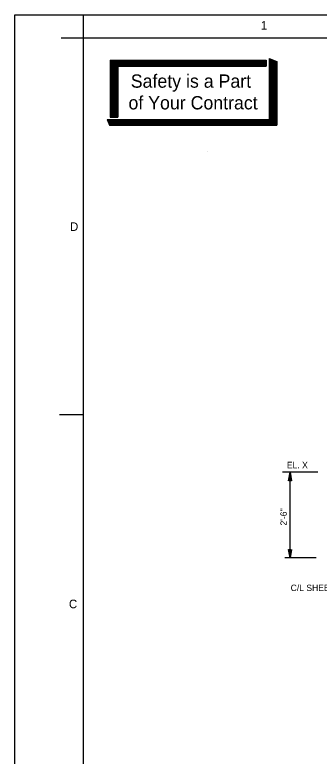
# Model space of a CAD drawing. Extents: x 44743.44 to 44747.1, y 44738.46 to 44741.29.
# Drawn here: x 44743.438 to 44743.993, y 44739.94 to 44741.292 of the extents above; entities that cross this region are included whole.
import ezdxf

# ---------------------------------------------------------------- set-up
doc = ezdxf.new("R2010")
doc.units = 0
for name, color, linetype in [('Level 1', 7, 'Continuous'), ('Level 10', 7, 'Continuous'), ('Level 9', 7, 'Continuous'), ('S-ANNO-TEXT', 7, 'Continuous')]:
    doc.layers.add(name, color=color, linetype=linetype)

msp = doc.modelspace()

# ---------------------------------------------------------------- linework, layer by layer
at = {"layer": 'Level 1'}
for p, q in [((44743.9904, 44740.4576), (44743.9264, 44740.4576)), ((44743.9399, 44740.3015), (44743.9399, 44740.4576)), ((44743.9399, 44740.4576), (44743.9399, 44740.4576)), ((44743.9399, 44740.4533), (44743.9399, 44740.4533)), ((44743.9877, 44740.3015), (44743.9303, 44740.3015)), ((44743.9399, 44740.3058), (44743.9399, 44740.3058)), ((44743.9399, 44740.3015), (44743.9399, 44740.3015))]:
    msp.add_line(p, q, dxfattribs=at)
msp.add_lwpolyline([(44743.438, 44741.2918), (44747.1047, 44741.2918), (44747.1047, 44738.4578), (44743.438, 44738.4578)], close=True, dxfattribs=at)
for points in [[(44743.9373, 44740.4421), (44743.9399, 44740.4576), (44743.9425, 44740.4421), (44743.938, 44740.4421), (44743.9399, 44740.4533), (44743.9416, 44740.4427), (44743.9388, 44740.4427), (44743.9399, 44740.4491), (44743.9408, 44740.4434), (44743.9396, 44740.4434), (44743.9399, 44740.4448)], [(44743.9425, 44740.317), (44743.9399, 44740.3015), (44743.9373, 44740.317), (44743.9417, 44740.317), (44743.9399, 44740.3058), (44743.9381, 44740.3164), (44743.941, 44740.3164), (44743.9399, 44740.31), (44743.939, 44740.3157), (44743.9401, 44740.3157), (44743.9399, 44740.3143)]]:
    msp.add_lwpolyline(points, dxfattribs=at)
at = {"layer": 'Level 10'}
for p, q in [((44743.563, 44741.2498), (44743.563, 44741.2918)), ((44743.5223, 44741.2498), (44743.5626, 44741.2498)), ((44743.612, 44741.2089), (44743.8967, 44741.2089)), ((44743.612, 44741.2089), (44743.612, 44741.1055)), ((44743.612, 44741.2076), (44743.8967, 44741.2076)), ((44743.612, 44741.2064), (44743.8967, 44741.2064)), ((44743.6133, 44741.2089), (44743.6133, 44741.1055)), ((44743.6146, 44741.2089), (44743.6146, 44741.1055)), ((44743.6159, 44741.2089), (44743.6159, 44741.1055)), ((44743.6172, 44741.2089), (44743.6172, 44741.1055)), ((44743.6185, 44741.2089), (44743.6185, 44741.1055)), ((44743.6198, 44741.2089), (44743.6198, 44741.1055)), ((44743.6211, 44741.2089), (44743.6211, 44741.1055)), ((44743.6224, 44741.2089), (44743.6224, 44741.1055)), ((44743.6237, 44741.2089), (44743.6237, 44741.1055)), ((44743.625, 44741.2089), (44743.625, 44741.1055)), ((44743.8967, 44741.2089), (44743.8967, 44741.1985)), ((44743.902, 44741.212), (44743.902, 44741.1009)), ((44743.902, 44741.212), (44743.9159, 44741.2069)), ((44743.9029, 44741.2117), (44743.9029, 44741.0904)), ((44743.9042, 44741.2112), (44743.9042, 44741.0904)), ((44743.9055, 44741.2107), (44743.9055, 44741.0904)), ((44743.9068, 44741.2102), (44743.9068, 44741.0904)), ((44743.9081, 44741.2098), (44743.9081, 44741.0904)), ((44743.9094, 44741.2093), (44743.9094, 44741.0904)), ((44743.9107, 44741.2088), (44743.9107, 44741.0904)), ((44743.912, 44741.2083), (44743.912, 44741.0904)), ((44743.9133, 44741.2079), (44743.9133, 44741.0904)), ((44743.9146, 44741.2069), (44743.9146, 44741.0904)), ((44743.9159, 44741.2069), (44743.9159, 44741.0904)), ((44743.612, 44741.205), (44743.8967, 44741.205)), ((44743.612, 44741.2037), (44743.8967, 44741.2037)), ((44743.612, 44741.2024), (44743.8967, 44741.2024)), ((44743.612, 44741.2011), (44743.8967, 44741.2011)), ((44743.612, 44741.1999), (44743.8967, 44741.1999)), ((44743.6259, 44741.1985), (44743.8967, 44741.1985)), ((44743.6259, 44741.1985), (44743.6259, 44741.1055)), ((44743.6067, 44741.1009), (44743.902, 44741.1009)), ((44743.6067, 44741.1009), (44743.6106, 44741.0904)), ((44743.6072, 44741.0995), (44743.9029, 44741.0995)), ((44743.6077, 44741.0983), (44743.9029, 44741.0983)), ((44743.612, 44741.1055), (44743.6259, 44741.1055)), ((44743.6082, 44741.0969), (44743.9029, 44741.0969)), ((44743.6087, 44741.0956), (44743.9029, 44741.0956)), ((44743.6092, 44741.0944), (44743.9029, 44741.0944)), ((44743.6097, 44741.093), (44743.9029, 44741.093)), ((44743.6101, 44741.0918), (44743.9029, 44741.0918)), ((44743.6106, 44741.0904), (44743.9159, 44741.0904)), ((44743.5197, 44740.5628), (44743.5617, 44740.5628))]:
    msp.add_line(p, q, dxfattribs=at)
at = {"layer": 'Level 9'}
for p, q in [((44743.563, 44738.4998), (44743.563, 44741.2498)), ((44743.563, 44741.2498), (44746.8337, 44741.2498))]:
    msp.add_line(p, q, dxfattribs=at)
at = {"layer": 'S-ANNO-TEXT'}
msp.add_line((44743.7893, 44741.0426), (44743.7893, 44741.0426), dxfattribs=at)

# ---------------------------------------------------------------- texts
at = {"layer": 'Level 1'}
for s, p in [('1', (44743.8867, 44741.2648)), ('D', (44743.5387, 44740.8978)), ('C', (44743.5367, 44740.2098))]:
    msp.add_text(s, height=0.0156, dxfattribs=at).set_placement(p)
at = {"layer": 'Level 10'}
for s, p in [('Safety is a Part', (44743.6495, 44741.1589)), ('of Your Contract', (44743.6453, 44741.1194))]:
    msp.add_text(s, height=0.024198, dxfattribs=at).set_placement(p)
at = {"layer": 'S-ANNO-TEXT'}
for s, height, p in [('EL. X', 0.01167, (44743.9342, 44740.4651)), ('C/L SHEET PILING', 0.011667, (44743.9411, 44740.2411))]:
    msp.add_text(s, height=height, dxfattribs=at).set_placement(p)
msp.add_text("2'-6''", height=0.01167, rotation=90, dxfattribs=at).set_placement((44743.934, 44740.3606))

doc.saveas('drawing.dxf')
